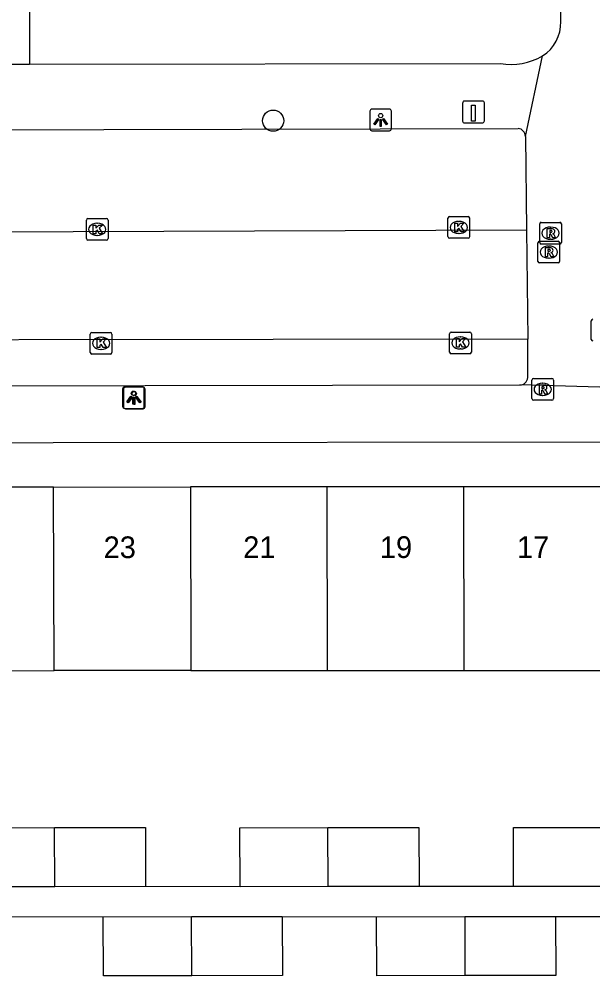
# Model space of a CAD drawing. Extents: x 160732 to 162105, y 387428 to 388479.
# Drawn here: x 161191.77 to 161218.22, y 388209.28 to 388253.41 of the extents above; entities that cross this region are included whole.
import ezdxf

# ---------------------------------------------------------------- set-up
doc = ezdxf.new("R2010")
doc.units = 0
for name, color, linetype in [('IMGEO_Boom', 7, 'Continuous'), ('IMGEO_Kolk', 7, 'Continuous'), ('IMGEO_Laadpaal', 7, 'Continuous'), ('IMGEO_Lichtpunt', 7, 'Continuous'), ('IMGEO_Pand', 7, 'Continuous'), ('IMGEO_Pand_nummerreeks', 7, 'Continuous'), ('IMGEO_Rijbaan_lokaal_open', 7, 'Continuous'), ('IMGEO_Rioolput', 7, 'Continuous'), ('IMGEO_Voetpad_open', 7, 'Continuous')]:
    doc.layers.add(name, color=color, linetype=linetype)

msp = doc.modelspace()

# ---------------------------------------------------------------- linework, layer by layer
at = {"layer": 'IMGEO_Boom'}
msp.add_circle((161203.483, 388248.723), 0.489, dxfattribs=at)
at = {"layer": 'IMGEO_Kolk'}
for p, q in [((161194.87, 388243.285), (161194.87, 388244.137)), ((161194.945, 388244.211), (161195.797, 388244.211)), ((161195.871, 388244.137), (161195.871, 388243.285)), ((161211.542, 388243.374), (161211.542, 388244.226)), ((161211.617, 388244.3), (161212.469, 388244.3)), ((161212.03, 388244.08), (161212.055, 388244.08)), ((161212.543, 388244.226), (161212.543, 388243.374)), ((161195.358, 388243.991), (161195.383, 388243.991)), ((161195.797, 388243.211), (161194.945, 388243.211)), ((161195.381, 388243.431), (161195.356, 388243.431)), ((161212.469, 388243.3), (161211.617, 388243.3)), ((161212.053, 388243.52), (161212.028, 388243.52)), ((161195.05, 388238.029), (161195.05, 388238.881)), ((161195.125, 388238.955), (161195.977, 388238.955)), ((161196.051, 388238.881), (161196.051, 388238.029)), ((161211.619, 388238.046), (161211.619, 388238.898)), ((161211.694, 388238.972), (161212.546, 388238.972)), ((161212.62, 388238.898), (161212.62, 388238.046)), ((161195.538, 388238.735), (161195.563, 388238.735)), ((161212.107, 388238.752), (161212.132, 388238.752)), ((161195.977, 388237.955), (161195.125, 388237.955)), ((161195.561, 388238.175), (161195.536, 388238.175)), ((161212.546, 388237.972), (161211.694, 388237.972)), ((161212.13, 388238.192), (161212.105, 388238.192))]:
    msp.add_line(p, q, dxfattribs=at)
for points in [[(161194.87, 388243.285), (161194.87, 388244.137)], [(161194.945, 388244.211), (161195.797, 388244.211)], [(161195.871, 388244.137), (161195.871, 388243.285)], [(161211.542, 388243.374), (161211.542, 388244.226)], [(161211.617, 388244.3), (161212.469, 388244.3)], [(161212.543, 388244.226), (161212.543, 388243.374)], [(161195.191, 388243.911), (161195.314, 388243.911), (161195.314, 388243.76), (161195.444, 388243.911), (161195.608, 388243.911), (161195.462, 388243.76), (161195.615, 388243.511), (161195.463, 388243.511), (161195.378, 388243.675), (161195.314, 388243.608), (161195.314, 388243.511), (161195.191, 388243.511), (161195.191, 388243.911)], [(161211.863, 388244), (161211.986, 388244), (161211.986, 388243.849), (161212.116, 388244), (161212.28, 388244), (161212.134, 388243.849), (161212.287, 388243.6), (161212.135, 388243.6), (161212.05, 388243.764), (161211.986, 388243.697), (161211.986, 388243.6), (161211.863, 388243.6), (161211.863, 388244)], [(161195.797, 388243.211), (161194.945, 388243.211)], [(161212.469, 388243.3), (161211.617, 388243.3)], [(161195.05, 388238.029), (161195.05, 388238.881)], [(161195.125, 388238.955), (161195.977, 388238.955)], [(161196.051, 388238.881), (161196.051, 388238.029)], [(161211.619, 388238.046), (161211.619, 388238.898)], [(161211.694, 388238.972), (161212.546, 388238.972)], [(161212.62, 388238.898), (161212.62, 388238.046)], [(161195.371, 388238.655), (161195.494, 388238.655), (161195.494, 388238.504), (161195.624, 388238.655), (161195.788, 388238.655), (161195.642, 388238.504), (161195.795, 388238.255), (161195.643, 388238.255), (161195.558, 388238.419), (161195.494, 388238.352), (161195.494, 388238.255), (161195.371, 388238.255), (161195.371, 388238.655)], [(161211.94, 388238.672), (161212.063, 388238.672), (161212.063, 388238.521), (161212.193, 388238.672), (161212.357, 388238.672), (161212.211, 388238.521), (161212.364, 388238.272), (161212.212, 388238.272), (161212.127, 388238.436), (161212.063, 388238.369), (161212.063, 388238.272), (161211.94, 388238.272), (161211.94, 388238.672)], [(161195.977, 388237.955), (161195.125, 388237.955)], [(161212.546, 388237.972), (161211.694, 388237.972)]]:
    msp.add_lwpolyline(points, dxfattribs=at)
for centre, start, end in [((161194.947, 388244.135), 91.552, 178.448), ((161194.947, 388244.135), 91.552, 178.448), ((161195.795, 388244.135), 1.552, 88.448), ((161195.795, 388244.135), 1.552, 88.448), ((161211.619, 388244.224), 91.552, 178.448), ((161211.619, 388244.224), 91.552, 178.448), ((161212.467, 388244.224), 1.552, 88.448), ((161212.467, 388244.224), 1.552, 88.448), ((161194.947, 388243.287), 181.552, 268.448), ((161194.947, 388243.287), 181.552, 268.448), ((161195.795, 388243.287), 271.552, 358.448), ((161195.795, 388243.287), 271.552, 358.448), ((161211.619, 388243.376), 181.552, 268.448), ((161211.619, 388243.376), 181.552, 268.448), ((161212.467, 388243.376), 271.552, 358.448), ((161212.467, 388243.376), 271.552, 358.448), ((161195.127, 388238.879), 91.552, 178.448), ((161195.127, 388238.879), 91.552, 178.448), ((161195.975, 388238.879), 1.552, 88.448), ((161195.975, 388238.879), 1.552, 88.448), ((161211.696, 388238.896), 91.552, 178.448), ((161211.696, 388238.896), 91.552, 178.448), ((161212.544, 388238.896), 1.552, 88.448), ((161212.544, 388238.896), 1.552, 88.448), ((161195.127, 388238.031), 181.552, 268.448), ((161195.127, 388238.031), 181.552, 268.448), ((161195.975, 388238.031), 271.552, 358.448), ((161195.975, 388238.031), 271.552, 358.448), ((161211.696, 388238.048), 181.552, 268.448), ((161211.696, 388238.048), 181.552, 268.448), ((161212.544, 388238.048), 271.552, 358.448), ((161212.544, 388238.048), 271.552, 358.448)]:
    msp.add_arc(centre, 0.0765, start, end, dxfattribs=at)
for centre, major_axis, ratio, start_param, end_param in [((161212.029, 388243.8), (-0.387, 0.002), 0.722429, 4.712389, 7.853982), ((161212.054, 388243.8), (-0.39, 0.002), 0.717154, 1.570796, 4.712389), ((161195.357, 388243.711), (-0.387, 0.002), 0.722429, 4.712389, 7.853982), ((161195.382, 388243.711), (-0.39, 0.002), 0.717154, 1.570796, 4.712389), ((161195.537, 388238.455), (-0.387, 0.002), 0.722429, 4.712389, 7.853982), ((161195.562, 388238.455), (-0.39, 0.002), 0.717154, 1.570796, 4.712389), ((161212.106, 388238.472), (-0.387, 0.002), 0.722429, 4.712389, 7.853982), ((161212.131, 388238.472), (-0.39, 0.002), 0.717154, 1.570796, 4.712389)]:
    msp.add_ellipse(centre, major_axis=major_axis, ratio=ratio, start_param=start_param, end_param=end_param, dxfattribs=at)
at = {"layer": 'IMGEO_Laadpaal'}
for p, q in [((161212.22, 388249.542), (161212.22, 388248.701)), ((161212.22, 388249.542), (161212.22, 388248.701)), ((161213.136, 388249.626), (161212.295, 388249.626)), ((161213.136, 388249.626), (161212.295, 388249.626)), ((161213.22, 388248.71), (161213.22, 388249.551)), ((161213.22, 388248.71), (161213.22, 388249.551)), ((161212.304, 388248.626), (161213.145, 388248.626)), ((161212.304, 388248.626), (161213.145, 388248.626))]:
    msp.add_line(p, q, dxfattribs=at)
msp.add_lwpolyline([(161212.635, 388249.439), (161212.795, 388249.439), (161212.795, 388248.706), (161212.635, 388248.706), (161212.635, 388249.439)], dxfattribs=at)
for centre, start, end in [((161212.298, 388249.548), 92.4484, 184.2845), ((161212.298, 388249.548), 92.4484, 184.2845), ((161213.142, 388249.548), 2.4484, 94.2845), ((161213.142, 388249.548), 2.4484, 94.2845), ((161212.298, 388248.704), 182.4484, 274.2845), ((161212.298, 388248.704), 182.4484, 274.2845), ((161213.142, 388248.704), 272.4484, 4.2845), ((161213.142, 388248.704), 272.4484, 4.2845)]:
    msp.add_arc(centre, 0.0779, start, end, dxfattribs=at)
at = {"layer": 'IMGEO_Lichtpunt'}
for p, q in [((161207.941, 388249.163), (161207.941, 388248.356)), ((161207.941, 388249.163), (161207.941, 388248.356)), ((161208.843, 388249.258), (161208.035, 388249.258)), ((161208.843, 388249.258), (161208.035, 388249.258)), ((161208.937, 388248.356), (161208.937, 388249.163)), ((161208.937, 388248.356), (161208.937, 388249.163)), ((161208.035, 388248.262), (161208.843, 388248.262)), ((161208.035, 388248.262), (161208.843, 388248.262)), ((161196.544, 388236.349), (161196.544, 388235.542)), ((161196.544, 388236.349), (161196.544, 388235.542)), ((161196.58, 388236.334), (161196.58, 388235.527)), ((161196.58, 388236.334), (161196.58, 388235.527)), ((161197.446, 388236.444), (161196.638, 388236.444)), ((161197.446, 388236.444), (161196.638, 388236.444)), ((161197.482, 388236.429), (161196.674, 388236.429)), ((161197.482, 388236.429), (161196.674, 388236.429)), ((161197.54, 388235.542), (161197.54, 388236.349)), ((161197.54, 388235.542), (161197.54, 388236.349)), ((161197.576, 388235.527), (161197.576, 388236.334)), ((161197.576, 388235.527), (161197.576, 388236.334)), ((161196.638, 388235.448), (161197.446, 388235.448)), ((161196.638, 388235.448), (161197.446, 388235.448)), ((161196.674, 388235.433), (161197.482, 388235.433)), ((161196.674, 388235.433), (161197.482, 388235.433))]:
    msp.add_line(p, q, dxfattribs=at)
for points in [[(161208.315, 388248.827), (161208.354, 388248.799), (161208.166, 388248.537), (161208.128, 388248.564), (161208.315, 388248.827)], [(161208.417, 388248.779), (161208.464, 388248.779), (161208.464, 388248.457), (161208.417, 388248.457), (161208.417, 388248.779)], [(161208.527, 388248.799), (161208.565, 388248.826), (161208.752, 388248.564), (161208.713, 388248.536), (161208.527, 388248.799)], [(161196.918, 388236.013), (161196.957, 388235.985), (161196.769, 388235.723), (161196.731, 388235.75), (161196.918, 388236.013)], [(161196.954, 388235.998), (161196.993, 388235.97), (161196.805, 388235.708), (161196.767, 388235.735), (161196.954, 388235.998)], [(161197.02, 388235.965), (161197.067, 388235.965), (161197.067, 388235.643), (161197.02, 388235.643), (161197.02, 388235.965)], [(161197.056, 388235.95), (161197.103, 388235.95), (161197.103, 388235.628), (161197.056, 388235.628), (161197.056, 388235.95)], [(161197.13, 388235.985), (161197.168, 388236.012), (161197.355, 388235.75), (161197.316, 388235.722), (161197.13, 388235.985)], [(161197.166, 388235.97), (161197.204, 388235.997), (161197.391, 388235.735), (161197.352, 388235.707), (161197.166, 388235.97)]]:
    msp.add_lwpolyline(points, dxfattribs=at)
for centre in [(161208.44, 388248.961), (161197.043, 388236.147), (161197.079, 388236.132)]:
    msp.add_circle(centre, 0.0994, dxfattribs=at)
for centre, start, end in [((161208.035, 388249.163), 90, 180), ((161208.035, 388249.163), 90, 180), ((161208.843, 388249.163), 0, 90), ((161208.843, 388249.163), 0, 90), ((161208.035, 388248.356), 180, 270), ((161208.035, 388248.356), 180, 270), ((161208.843, 388248.356), 270, 0), ((161208.843, 388248.356), 270, 360), ((161196.638, 388236.349), 90, 180), ((161196.638, 388236.349), 90, 180), ((161196.674, 388236.334), 90, 180), ((161196.674, 388236.334), 90, 180), ((161197.446, 388236.349), 0, 90), ((161197.446, 388236.349), 0, 90), ((161197.482, 388236.334), 0, 90), ((161197.482, 388236.334), 0, 90), ((161196.638, 388235.542), 180, 270), ((161196.638, 388235.542), 180, 270), ((161196.674, 388235.527), 180, 270), ((161196.674, 388235.527), 180, 270), ((161197.446, 388235.542), 270, 0), ((161197.446, 388235.542), 270, 360), ((161197.482, 388235.527), 270, 0), ((161197.482, 388235.527), 270, 360)]:
    msp.add_arc(centre, 0.0946, start, end, dxfattribs=at)
at = {"layer": 'IMGEO_Pand'}
for points in [[(161193.359, 388231.824), (161187.063, 388231.821)], [(161193.359, 388231.824), (161199.665, 388231.827)], [(161193.382, 388223.354), (161193.359, 388231.824)], [(161205.971, 388231.829), (161199.665, 388231.827)], [(161199.665, 388231.827), (161199.689, 388223.357)], [(161212.277, 388231.832), (161205.971, 388231.829)], [(161205.992, 388223.36), (161205.971, 388231.829)], [(161218.583, 388231.835), (161212.277, 388231.832)], [(161212.293, 388223.363), (161212.277, 388231.832)], [(161187.087, 388223.352), (161193.382, 388223.354)], [(161199.689, 388223.357), (161193.382, 388223.354)], [(161199.689, 388223.357), (161205.992, 388223.36)], [(161205.992, 388223.36), (161212.293, 388223.363)], [(161212.293, 388223.363), (161218.598, 388223.366)], [(161189.346, 388213.381), (161189.342, 388216.105), (161193.402, 388216.112)], [(161193.402, 388216.112), (161197.594, 388216.119), (161197.599, 388213.395)], [(161193.409, 388213.388), (161193.402, 388216.112)], [(161201.956, 388213.387), (161201.952, 388216.111), (161206.01, 388216.118)], [(161206.01, 388216.118), (161210.204, 388216.125), (161210.209, 388213.401)], [(161206.017, 388213.394), (161206.01, 388216.118)], [(161214.562, 388213.393), (161214.558, 388216.117), (161218.611, 388216.124)], [(161193.409, 388213.388), (161189.346, 388213.381)], [(161197.599, 388213.395), (161193.409, 388213.388)], [(161206.017, 388213.394), (161201.956, 388213.387)], [(161210.209, 388213.401), (161206.017, 388213.394)], [(161218.616, 388213.4), (161214.562, 388213.393)], [(161195.649, 388211.999), (161199.721, 388212.006)], [(161199.729, 388209.282), (161195.653, 388209.275), (161195.649, 388211.999)], [(161199.721, 388212.006), (161203.901, 388212.013)], [(161199.729, 388209.282), (161199.721, 388212.006)], [(161203.901, 388212.013), (161203.906, 388209.289), (161199.729, 388209.282)], [(161208.253, 388212.005), (161212.314, 388212.012)], [(161212.32, 388209.288), (161208.257, 388209.281), (161208.253, 388212.005)], [(161212.314, 388212.012), (161216.505, 388212.019)], [(161212.314, 388212.012), (161212.32, 388209.288)], [(161216.505, 388212.019), (161216.51, 388209.295), (161212.32, 388209.288)]]:
    msp.add_lwpolyline(points, dxfattribs=at)
at = {"layer": 'IMGEO_Rijbaan_lokaal_open'}
for points in [[(161169.177, 388243.522), (161215.171, 388243.69)], [(161215.171, 388243.69), (161215.218, 388238.652)], [(161215.218, 388238.652), (161168.262, 388238.58)]]:
    msp.add_lwpolyline(points, dxfattribs=at)
at = {"layer": 'IMGEO_Rioolput'}
for p, q in [((161215.771, 388243.108), (161215.771, 388243.96)), ((161215.846, 388244.034), (161216.698, 388244.034)), ((161216.259, 388243.814), (161216.284, 388243.814)), ((161216.772, 388243.96), (161216.772, 388243.108)), ((161216.282, 388243.254), (161216.257, 388243.254)), ((161215.691, 388242.235), (161215.691, 388243.087)), ((161215.766, 388243.161), (161216.618, 388243.161)), ((161216.698, 388243.034), (161215.846, 388243.034)), ((161216.179, 388242.941), (161216.204, 388242.941)), ((161216.692, 388243.087), (161216.692, 388242.235)), ((161216.202, 388242.381), (161216.177, 388242.381)), ((161216.618, 388242.161), (161215.766, 388242.161)), ((161218.148, 388238.636), (161218.148, 388239.488)), ((161215.41, 388235.904), (161215.41, 388236.756)), ((161215.485, 388236.83), (161216.337, 388236.83)), ((161215.898, 388236.61), (161215.923, 388236.61)), ((161216.411, 388236.756), (161216.411, 388235.904)), ((161216.337, 388235.83), (161215.485, 388235.83)), ((161215.921, 388236.05), (161215.896, 388236.05))]:
    msp.add_line(p, q, dxfattribs=at)
for points in [[(161215.771, 388243.108), (161215.771, 388243.96)], [(161215.846, 388244.034), (161216.698, 388244.034)], [(161216.36, 388243.732), (161216.108, 388243.734), (161216.108, 388243.334)], [(161216.286, 388243.653), (161216.232, 388243.653), (161216.232, 388243.572)], [(161216.772, 388243.96), (161216.772, 388243.108)], [(161216.108, 388243.334), (161216.232, 388243.334), (161216.232, 388243.496), (161216.243, 388243.496)], [(161216.232, 388243.572), (161216.284, 388243.572)], [(161216.29, 388243.467), (161216.361, 388243.334), (161216.501, 388243.334), (161216.436, 388243.46)], [(161215.691, 388242.235), (161215.691, 388243.087)], [(161215.766, 388243.161), (161216.618, 388243.161)], [(161216.698, 388243.034), (161215.846, 388243.034)], [(161216.28, 388242.859), (161216.028, 388242.861), (161216.028, 388242.461)], [(161216.206, 388242.78), (161216.152, 388242.78), (161216.152, 388242.699)], [(161216.692, 388243.087), (161216.692, 388242.235)], [(161216.028, 388242.461), (161216.152, 388242.461), (161216.152, 388242.623), (161216.163, 388242.623)], [(161216.152, 388242.699), (161216.204, 388242.699)], [(161216.21, 388242.594), (161216.281, 388242.461), (161216.421, 388242.461), (161216.356, 388242.587)], [(161216.618, 388242.161), (161215.766, 388242.161)], [(161218.148, 388238.636), (161218.148, 388239.488)], [(161215.41, 388235.904), (161215.41, 388236.756)], [(161215.485, 388236.83), (161216.337, 388236.83)], [(161216.411, 388236.756), (161216.411, 388235.904)], [(161215.999, 388236.528), (161215.747, 388236.53), (161215.747, 388236.13)], [(161215.747, 388236.13), (161215.871, 388236.13), (161215.871, 388236.292), (161215.882, 388236.292)], [(161215.925, 388236.449), (161215.871, 388236.449), (161215.871, 388236.368)], [(161215.871, 388236.368), (161215.923, 388236.368)], [(161215.929, 388236.263), (161216, 388236.13), (161216.14, 388236.13), (161216.075, 388236.256)], [(161216.337, 388235.83), (161215.485, 388235.83)]]:
    msp.add_lwpolyline(points, dxfattribs=at)
for centre, radius, start, end in [((161215.848, 388243.958), 0.0765, 91.552, 178.448), ((161215.848, 388243.958), 0.0765, 91.552, 178.448), ((161216.292, 388243.557), 0.0964, 77.0061, 93.1865), ((161216.306, 388243.614), 0.0378, 276.6634, 79.6772), ((161216.359, 388243.622), 0.109, 350.3612, 89.416), ((161216.696, 388243.958), 0.0765, 1.552, 88.448), ((161216.696, 388243.958), 0.0765, 1.552, 88.448), ((161216.242, 388243.443), 0.0533, 26.0293, 88.6989), ((161216.268, 388243.761), 0.19, 274.7715, 282.9687), ((161216.357, 388243.622), 0.112, 277.5842, 350.9817), ((161216.341, 388243.407), 0.108, 29.5134, 73.7905), ((161215.768, 388243.085), 0.0765, 91.552, 178.448), ((161215.768, 388243.085), 0.0765, 91.552, 178.448), ((161215.848, 388243.11), 0.0765, 181.552, 268.448), ((161215.848, 388243.11), 0.0765, 181.552, 268.448), ((161216.212, 388242.684), 0.0964, 77.0061, 93.1865), ((161216.226, 388242.741), 0.0378, 276.6634, 79.6772), ((161216.279, 388242.749), 0.109, 350.3612, 89.416), ((161216.616, 388243.085), 0.0765, 1.552, 88.448), ((161216.616, 388243.085), 0.0765, 1.552, 88.448), ((161216.696, 388243.11), 0.0765, 271.552, 358.448), ((161216.696, 388243.11), 0.0765, 271.552, 358.448), ((161216.162, 388242.57), 0.0533, 26.0293, 88.6989), ((161216.188, 388242.888), 0.19, 274.7715, 282.9687), ((161216.277, 388242.749), 0.112, 277.5842, 350.9817), ((161216.261, 388242.534), 0.108, 29.5134, 73.7905), ((161215.768, 388242.237), 0.0765, 181.552, 268.448), ((161215.768, 388242.237), 0.0765, 181.552, 268.448), ((161216.616, 388242.237), 0.0765, 271.552, 358.448), ((161216.616, 388242.237), 0.0765, 271.552, 358.448), ((161218.225, 388239.486), 0.0765, 91.552, 178.448), ((161218.225, 388239.486), 0.0765, 91.552, 178.448), ((161218.225, 388238.638), 0.0765, 181.552, 268.448), ((161218.225, 388238.638), 0.0765, 181.552, 268.448), ((161215.487, 388236.754), 0.0765, 91.552, 178.448), ((161215.487, 388236.754), 0.0765, 91.552, 178.448), ((161216.335, 388236.754), 0.0765, 1.552, 88.448), ((161216.335, 388236.754), 0.0765, 1.552, 88.448), ((161215.881, 388236.239), 0.0533, 26.0293, 88.6989), ((161215.907, 388236.557), 0.19, 274.7715, 282.9687), ((161215.931, 388236.353), 0.0964, 77.0061, 93.1865), ((161215.945, 388236.41), 0.0378, 276.6634, 79.6772), ((161215.998, 388236.418), 0.109, 350.3612, 89.416), ((161215.996, 388236.418), 0.112, 277.5842, 350.9817), ((161215.98, 388236.203), 0.108, 29.5134, 73.7905), ((161215.487, 388235.906), 0.0765, 181.552, 268.448), ((161215.487, 388235.906), 0.0765, 181.552, 268.448), ((161216.335, 388235.906), 0.0765, 271.552, 358.448), ((161216.335, 388235.906), 0.0765, 271.552, 358.448)]:
    msp.add_arc(centre, radius, start, end, dxfattribs=at)
for centre, major_axis, ratio, start_param, end_param in [((161216.258, 388243.534), (-0.387, 0.002), 0.722429, 4.712389, 7.853982), ((161216.283, 388243.534), (-0.39, 0.002), 0.717154, 1.570796, 4.712389), ((161216.178, 388242.661), (-0.387, 0.002), 0.722429, 4.712389, 7.853982), ((161216.203, 388242.661), (-0.39, 0.002), 0.717154, 1.570796, 4.712389), ((161215.897, 388236.33), (-0.387, 0.002), 0.722429, 4.712389, 7.853982), ((161215.922, 388236.33), (-0.39, 0.002), 0.717154, 1.570796, 4.712389)]:
    msp.add_ellipse(centre, major_axis=major_axis, ratio=ratio, start_param=start_param, end_param=end_param, dxfattribs=at)
at = {"layer": 'IMGEO_Voetpad_open'}
for points in [[(161216.746, 388253.294), (161216.727, 388258.628)], [(161192.238, 388256.496), (161192.244, 388251.336)], [(161215.117, 388247.997), (161215.903, 388251.707)], [(161190.676, 388251.334), (161192.244, 388251.336)], [(161192.244, 388251.336), (161213.961, 388251.36)], [(161170.135, 388244.535), (161170.179, 388248.26), (161214.781, 388248.368)], [(161215.117, 388247.997), (161215.171, 388243.69)], [(161215.222, 388236.87), (161215.218, 388238.652)], [(161171.645, 388236.464), (161214.856, 388236.533)], [(161221.86, 388236.351), (161221.695, 388236.335), (161214.856, 388236.533)], [(161168.029, 388233.843), (161243.914, 388233.947)], [(161201.956, 388213.387), (161197.599, 388213.395)], [(161214.562, 388213.393), (161210.209, 388213.401)], [(161191.299, 388212.008), (161195.649, 388211.999)], [(161203.901, 388212.013), (161208.253, 388212.005)], [(161216.505, 388212.019), (161220.854, 388212.01)]]:
    msp.add_lwpolyline(points, dxfattribs=at)
for centre, radius, start, end in [((161214.896, 388253.259), 1.85, 302.9652, 1.0811), ((161214.459, 388254.18), 2.863, 259.9801, 300.2815), ((161214.725, 388247.98), 0.392, 2.4966, 81.8352), ((161214.86, 388236.896), 0.363, 269.3474, 355.9282)]:
    msp.add_arc(centre, radius, start, end, dxfattribs=at)

# ---------------------------------------------------------------- texts
at = {"layer": 'IMGEO_Pand_nummerreeks'}
for s, p in [('23', (161195.665, 388228.545)), ('21', (161202.102, 388228.548)), ('19', (161208.403, 388228.551)), ('17', (161214.726, 388228.554))]:
    msp.add_text(s, height=1, rotation=0.0249, dxfattribs=at).set_placement(p)

doc.saveas('drawing.dxf')
